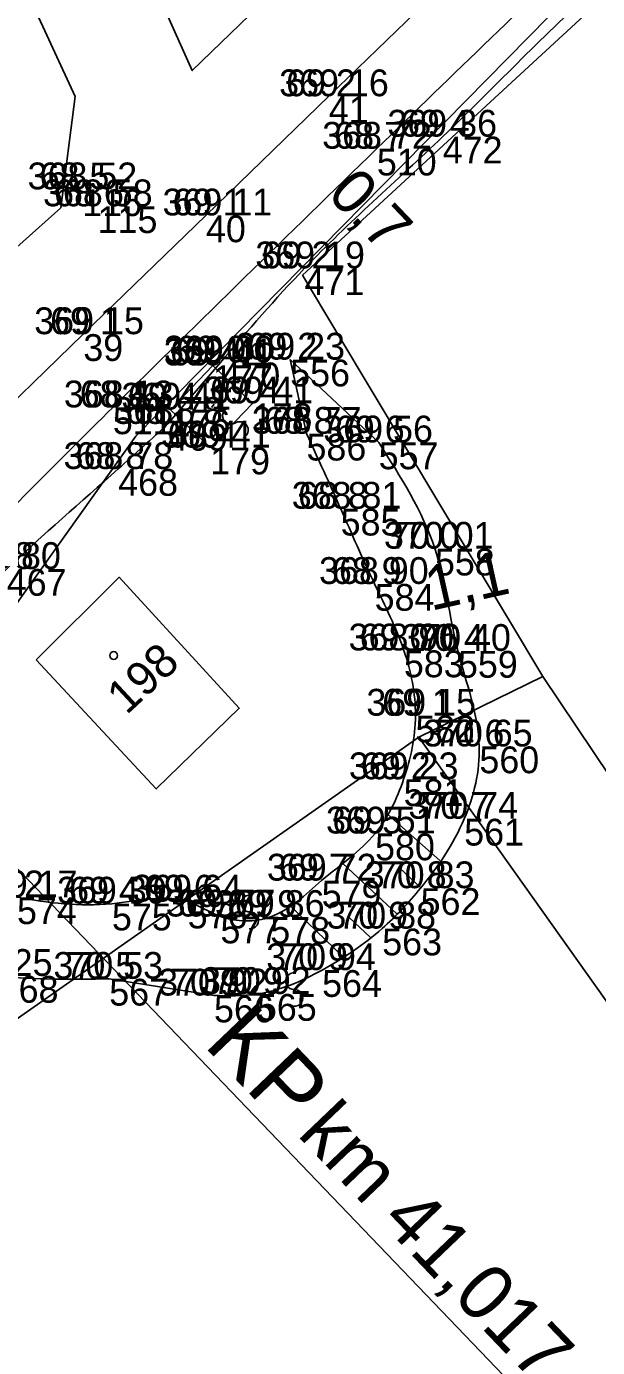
# Model space of a CAD drawing. Extents: x -514509 to -512782, y -1144610 to -1143439.
# Drawn here: x -514463.1 to -514437.5, y -1144579 to -1144519.8 of the extents above; entities that cross this region are included whole.
import ezdxf

# ---------------------------------------------------------------- set-up
doc = ezdxf.new("R2010")
doc.units = 0
for name, color, linetype in [('Vrstva 1', 7, 'Continuous'), ('Vrstva 10', 7, 'Continuous'), ('Vrstva 11', 7, 'Continuous'), ('Vrstva 18', 7, 'Continuous'), ('Vrstva 39', 7, 'Continuous'), ('Vrstva 57', 7, 'Continuous'), ('Vrstva 58', 7, 'Continuous'), ('Vrstva 59', 7, 'Continuous'), ('Vrstva 6', 7, 'Continuous'), ('Vrstva 60', 7, 'Continuous'), ('Vrstva 8', 7, 'Continuous'), ('Vrstva 9', 7, 'Continuous')]:
    doc.layers.add(name, color=color, linetype=linetype)

msp = doc.modelspace()

# ---------------------------------------------------------------- linework, layer by layer
at = {"layer": 'Vrstva 1'}
msp.add_lwpolyline([(-514486.959, -1144573.259), (-514486.512, -1144572.833), (-514479.3, -1144565.501), (-514471.808, -1144557.321), (-514458.154, -1144538.146), (-514438.738, -1144518.384)], dxfattribs=at)
at = {"layer": 'Vrstva 10'}
for points in [[(-514499.819, -1144558.314), (-514478.557, -1144543.138), (-514461.519, -1144527.903), (-514460.881, -1144522.921), (-514467.806, -1144507.951), (-514463.437, -1144504.318), (-514455.636, -1144521.761), (-514416.221, -1144483.68), (-514393.167, -1144461.734), (-514369.711, -1144436.746), (-514306.194, -1144376.041), (-514315.59, -1144367.645), (-514315.978, -1144364.474), (-514264.396, -1144333.352), (-514260.011, -1144328.496), (-514252.731, -1144315.601), (-514243.166, -1144315.871), (-514219.401, -1144293.726)], [(-514200.74, -1144295.636), (-514262.452, -1144355.017), (-514268.983, -1144370.755), (-514278.697, -1144366.838), (-514289.275, -1144383.939), (-514344.28, -1144437.349), (-514361.723, -1144450.643), (-514428.349, -1144510.282), (-514450.694, -1144530.929), (-514439.937, -1144548.904), (-514445.489, -1144551.626), (-514469.812, -1144568.673), (-514482.71, -1144578.196)], [(-514200.74, -1144295.636), (-514262.452, -1144355.017), (-514268.983, -1144370.755), (-514278.697, -1144366.838), (-514289.275, -1144383.939), (-514344.28, -1144437.349), (-514361.723, -1144450.643), (-514428.349, -1144510.282), (-514450.694, -1144530.929), (-514439.937, -1144548.904), (-514445.489, -1144551.626), (-514469.812, -1144568.673), (-514482.71, -1144578.196)], [(-514454.371, -1144534.844), (-514456.72, -1144537.59)], [(-514451.25, -1144534.708), (-514447.285, -1144538.424)], [(-514450.516, -1144538.027), (-514451.25, -1144534.708)], [(-514444.543, -1144557.155), (-514446.884, -1144555.083)], [(-514446.477, -1144559.546), (-514448.898, -1144557.287)], [(-514445.418, -1144558.36), (-514446.362, -1144557.473)], [(-514448.877, -1144561.467), (-514451.278, -1144559.151)], [(-514447.657, -1144560.601), (-514448.613, -1144559.702)], [(-514454.658, -1144563.198), (-514459.348, -1144562.45)]]:
    msp.add_lwpolyline(points, dxfattribs=at)
for points in [[(-514375.949, -1144459.095), (-514387.132, -1144469.854), (-514400.738, -1144482.57), (-514412.845, -1144493.748), (-514424.447, -1144503.796), (-514437.11, -1144515.375), (-514447.371, -1144525.258), (-514459.186, -1144536.848), (-514466.652, -1144544.376), (-514470.691, -1144548.585)], [(-514454.371, -1144534.844), (-514450.606, -1144530.619), (-514444.418, -1144524.718), (-514437.738, -1144518.212), (-514427.828, -1144509.829), (-514420.59, -1144502.963), (-514408.415, -1144492.628), (-514395.794, -1144481.427), (-514388.087, -1144474.529), (-514380.093, -1144467.923), (-514372.759, -1144462.078)], [(-514488.198, -1144571.819), (-514485.437, -1144569.212), (-514482.715, -1144566.566), (-514480.09, -1144563.83), (-514478.831, -1144562.413), (-514477.617, -1144560.954), (-514476.333, -1144559.296), (-514475.09, -1144557.61), (-514473.859, -1144555.916), (-514472.612, -1144554.233), (-514470.834, -1144551.888), (-514469.034, -1144549.558), (-514463.938, -1144544.087), (-514458.947, -1144539.607), (-514456.72, -1144537.59)], [(-514470.074, -1144558.067), (-514467.373, -1144558.131), (-514463.477, -1144558.796), (-514459.23, -1144559.085), (-514455.839, -1144558.992), (-514454.366, -1144559.66), (-514452.137, -1144559.677), (-514449.842, -1144558.049), (-514447.449, -1144555.942), (-514446.17, -1144553.512), (-514445.642, -1144550.659), (-514446.158, -1144547.737), (-514447.471, -1144544.76), (-514448.987, -1144541.391), (-514450.516, -1144538.027)], [(-514447.285, -1144538.424), (-514444.77, -1144543.177), (-514443.739, -1144547.762), (-514442.784, -1144552.042), (-514443.457, -1144555.285), (-514445.415, -1144558.39), (-514447.132, -1144560.198), (-514449.821, -1144562.057), (-514452.741, -1144563.134), (-514454.658, -1144563.198)], [(-514459.348, -1144562.45), (-514464.296, -1144562.322), (-514468.295, -1144561.563), (-514471.754, -1144560.638)]]:
    msp.add_spline(points, degree=3, dxfattribs=at)
at = {"layer": 'Vrstva 18'}
for centre, radius, start, end in [((-514453.899, -1144537.225), 0.376, 114.77011, 301.08124), ((-514453.506, -1144537.867), 0.377, 294.09407, 121.75728), ((-514453.055, -1144559.079), 0.376, 84.36247, 270.6736), ((-514453.042, -1144559.832), 0.377, 263.68642, 91.34964), ((-514451.071, -1144562.555), 0.376, 84.36247, 270.6736), ((-514451.058, -1144563.308), 0.377, 263.68642, 91.34964)]:
    msp.add_arc(centre, radius, start, end, dxfattribs=at)
at = {"layer": 'Vrstva 39'}
msp.add_lwpolyline([(-514471.348, -1144549.289), (-514439.942, -1144582.059)], dxfattribs=at)
at = {"layer": 'Vrstva 6'}
msp.add_line((-514454.776, -1144536.853), (-514454.648, -1144536.704), dxfattribs=at)
msp.add_lwpolyline([(-514493.711, -1144565.412), (-514492.396, -1144564.192), (-514486.631, -1144558.888), (-514481.255, -1144553.686), (-514473.947, -1144546.599), (-514470.451, -1144543.209), (-514465.565, -1144538.47), (-514460.514, -1144533.572), (-514455.022, -1144528.247), (-514449.52, -1144522.91), (-514443.898, -1144517.459)], dxfattribs=at)
msp.add_lwpolyline([(-514456.608, -1144536.955), (-514454.706, -1144534.97), (-514452.932, -1144536.669), (-514454.834, -1144538.654)], close=True, dxfattribs=at)
at = {"layer": 'Vrstva 60'}
for p, q in [((-514449.52, -1144522.91), (-514449.52, -1144522.91)), ((-514444.42, -1144524.72), (-514444.42, -1144524.72)), ((-514447.37, -1144525.26), (-514447.37, -1144525.26)), ((-514460.56, -1144527.08), (-514460.56, -1144527.08)), ((-514459.87, -1144527.84), (-514459.87, -1144527.84)), ((-514455.02, -1144528.25), (-514455.02, -1144528.25)), ((-514450.61, -1144530.62), (-514450.61, -1144530.62)), ((-514460.51, -1144533.57), (-514460.51, -1144533.57)), ((-514454.71, -1144534.97), (-514454.71, -1144534.97)), ((-514454.37, -1144534.84), (-514454.37, -1144534.84)), ((-514451.25, -1144534.71), (-514451.25, -1144534.71)), ((-514459.19, -1144536.85), (-514459.19, -1144536.85)), ((-514456.61, -1144536.95), (-514456.61, -1144536.95)), ((-514452.93, -1144536.67), (-514452.93, -1144536.67)), ((-514456.72, -1144537.59), (-514456.72, -1144537.59)), ((-514450.52, -1144538.03), (-514450.52, -1144538.03)), ((-514454.83, -1144538.65), (-514454.83, -1144538.65)), ((-514447.29, -1144538.42), (-514447.29, -1144538.42)), ((-514458.95, -1144539.61), (-514458.95, -1144539.61)), ((-514448.99, -1144541.39), (-514448.99, -1144541.39)), ((-514444.77, -1144543.18), (-514444.77, -1144543.18)), ((-514447.47, -1144544.76), (-514447.47, -1144544.76)), ((-514446.16, -1144547.74), (-514446.16, -1144547.74)), ((-514443.74, -1144547.76), (-514443.74, -1144547.76)), ((-514445.64, -1144550.66), (-514445.64, -1144550.66)), ((-514442.78, -1144552.04), (-514442.78, -1144552.04)), ((-514446.17, -1144553.51), (-514446.17, -1144553.51)), ((-514443.46, -1144555.28), (-514443.46, -1144555.28)), ((-514447.45, -1144555.94), (-514447.45, -1144555.94)), ((-514449.84, -1144558.05), (-514449.84, -1144558.05)), ((-514445.41, -1144558.39), (-514445.41, -1144558.39)), ((-514459.23, -1144559.08), (-514459.23, -1144559.08)), ((-514455.84, -1144558.99), (-514455.84, -1144558.99)), ((-514454.37, -1144559.66), (-514454.37, -1144559.66)), ((-514452.14, -1144559.68), (-514452.14, -1144559.68)), ((-514447.13, -1144560.2), (-514447.13, -1144560.2)), ((-514459.35, -1144562.45), (-514459.35, -1144562.45)), ((-514449.82, -1144562.06), (-514449.82, -1144562.06)), ((-514454.66, -1144563.2), (-514454.66, -1144563.2)), ((-514452.74, -1144563.13), (-514452.74, -1144563.13))]:
    msp.add_line(p, q, dxfattribs=at)
at = {"layer": 'Vrstva 8'}
msp.add_lwpolyline([(-514462.623, -1144548.157), (-514458.902, -1144544.458), (-514453.531, -1144550.331), (-514457.243, -1144553.945)], close=True, dxfattribs=at)
for points in [[(-514439.937, -1144548.904), (-514400.689, -1144607.426), (-514383.25, -1144597.943)], [(-514400.689, -1144607.426), (-514404.33, -1144609.596), (-514445.489, -1144551.626)]]:
    msp.add_lwpolyline(points, dxfattribs=at)
at = {"layer": 'Vrstva 9'}
msp.add_circle((-514459.149, -1144547.967), 0.175, dxfattribs=at)

# ---------------------------------------------------------------- texts
at = {"layer": 'Vrstva 11'}
for s, rotation, p in [('0,7', 313.64186, (-514449.647, -1144527.333)), ('1,1', 12.58002, (-514444.949, -1144545.969))]:
    msp.add_text(s, height=2, rotation=rotation, dxfattribs=at).set_placement(p)
at = {"layer": 'Vrstva 39'}
for s, height, p in [('KP', 3, (-514455.167, -1144565.423)), ('km 41,017', 2.5, (-514450.976, -1144569.442))]:
    msp.add_text(s, height=height, rotation=313.73264, dxfattribs=at).set_placement(p)
at = {"layer": 'Vrstva 57'}
for s, p in [('69 2 ', (-514451.434, -1144522.91)), ('69 4 ', (-514446.334, -1144524.72)), ('68 7 ', (-514449.278, -1144525.26)), ('68 5 ', (-514462.468, -1144527.08)), ('68 6 ', (-514461.818, -1144527.84)), ('69 1 ', (-514456.51, -1144528.25)), ('69 2 ', (-514452.524, -1144530.62)), ('69 1 ', (-514462, -1144533.57)), ('69 2 ', (-514453.164, -1144534.71)), ('69 4 ', (-514456.624, -1144534.97)), ('69 0 ', (-514456.35, -1144534.84)), ('68 1 ', (-514460.672, -1144536.85)), ('69 4 ', (-514458.524, -1144536.95)), ('69 4 ', (-514454.844, -1144536.67)), ('68 8 ', (-514458.628, -1144537.59)), ('68 8 ', (-514452.428, -1144538.03)), ('69 4 ', (-514456.744, -1144538.65)), ('69 6 ', (-514449.246, -1144538.42)), ('68 8 ', (-514460.858, -1144539.61)), ('68 8 ', (-514450.898, -1144541.39)), ('70 0 ', (-514446.796, -1144543.18)), ('68 8 ', (-514465.848, -1144544.09)), ('68 9 ', (-514449.383, -1144544.76)), ('69 0 ', (-514448.14, -1144547.74)), ('70 4 ', (-514445.7, -1144547.76)), ('69 1 ', (-514447.13, -1144550.66)), ('70 6 ', (-514444.782, -1144552.04)), ('69 2 ', (-514448.084, -1144553.51)), ('70 7 ', (-514445.42, -1144555.28)), ('69 5 ', (-514449.364, -1144555.94)), ('69 7 ', (-514451.754, -1144558.05)), ('70 8 ', (-514447.37, -1144558.39)), ('69 2 ', (-514465.394, -1144558.8)), ('69 4 ', (-514461.144, -1144559.08)), ('69 6 ', (-514457.796, -1144558.99)), ('69 8 ', (-514456.284, -1144559.66)), ('69 9 ', (-514454.06, -1144559.68)), ('70 9 ', (-514449.096, -1144560.2)), ('70 5 ', (-514461.31, -1144562.45)), ('70 9 ', (-514451.786, -1144562.06)), ('70 9 ', (-514454.706, -1144563.13)), ('70 9 ', (-514456.626, -1144563.2))]:
    msp.add_text(s, height=1.2, dxfattribs=at).set_placement(p)
at = {"layer": 'Vrstva 58'}
for s, p in [('369 16', (-514451.742, -1144522.91)), ('369 36', (-514446.898, -1144524.72)), ('368 72', (-514449.816, -1144525.26)), ('368 52', (-514463.006, -1144527.08)), ('368 58', (-514462.316, -1144527.84)), ('369 11', (-514456.963, -1144528.25)), ('369 19', (-514452.811, -1144530.62)), ('369 15', (-514462.708, -1144533.57)), ('369 23', (-514453.702, -1144534.71)), ('369 41', (-514456.908, -1144534.97)), ('369 00', (-514456.9, -1144534.84)), ('368 13', (-514461.38, -1144536.85)), ('369 41', (-514458.808, -1144536.95)), ('369 41', (-514455.128, -1144536.67)), ('368 78', (-514459.166, -1144537.59)), ('368 77', (-514452.966, -1144538.03)), ('369 41', (-514457.028, -1144538.65)), ('369 56', (-514449.768, -1144538.42)), ('368 78', (-514461.396, -1144539.61)), ('368 81', (-514451.18, -1144541.39)), ('370 01', (-514447.052, -1144543.18)), ('368 80', (-514466.424, -1144544.09)), ('368 90', (-514449.958, -1144544.76)), ('368 96', (-514448.634, -1144547.74)), ('370 40', (-514446.278, -1144547.76)), ('369 15', (-514447.838, -1144550.66)), ('370 65', (-514445.304, -1144552.04)), ('369 23', (-514448.622, -1144553.51)), ('370 74', (-514445.958, -1144555.28)), ('369 51', (-514449.648, -1144555.94)), ('369 72', (-514452.292, -1144558.05)), ('370 83', (-514447.908, -1144558.39)), ('369 17', (-514465.678, -1144558.8)), ('369 39', (-514461.686, -1144559.08)), ('369 64', (-514458.318, -1144558.99)), ('369 77', (-514456.822, -1144559.66)), ('369 86', (-514454.618, -1144559.68)), ('370 88', (-514449.628, -1144560.2)), ('370 25', (-514466.798, -1144562.32)), ('370 53', (-514461.848, -1144562.45)), ('370 94', (-514452.322, -1144562.06)), ('370 92', (-514455.242, -1144563.13)), ('370 92', (-514457.162, -1144563.2))]:
    msp.add_text(s, height=1.2, dxfattribs=at).set_placement(p)
at = {"layer": 'Vrstva 59'}
for s, p in [('41', (-514449.52, -1144524.11)), ('472', (-514444.42, -1144525.92)), ('510', (-514447.37, -1144526.46)), ('116', (-514460.56, -1144528.28)), ('115', (-514459.87, -1144529.04)), ('40', (-514455.02, -1144529.45)), ('471', (-514450.61, -1144531.82)), ('39', (-514460.51, -1144534.77)), ('177', (-514454.71, -1144536.17)), ('470', (-514454.37, -1144536.04)), ('556', (-514451.25, -1144535.91)), ('511', (-514459.19, -1144538.05)), ('176', (-514456.61, -1144538.15)), ('178', (-514452.93, -1144537.87)), ('469', (-514456.72, -1144538.79)), ('586', (-514450.52, -1144539.23)), ('179', (-514454.83, -1144539.85)), ('557', (-514447.29, -1144539.62)), ('468', (-514458.95, -1144540.81)), ('585', (-514448.99, -1144542.59)), ('558', (-514444.77, -1144544.38)), ('467', (-514463.94, -1144545.29)), ('584', (-514447.47, -1144545.96)), ('583', (-514446.16, -1144548.94)), ('559', (-514443.74, -1144548.96)), ('582', (-514445.64, -1144551.86)), ('560', (-514442.78, -1144553.24)), ('581', (-514446.17, -1144554.71)), ('561', (-514443.46, -1144556.48)), ('580', (-514447.45, -1144557.14)), ('579', (-514449.84, -1144559.25)), ('574', (-514463.48, -1144560)), ('562', (-514445.41, -1144559.59)), ('575', (-514459.23, -1144560.28)), ('576', (-514455.84, -1144560.19)), ('577', (-514454.37, -1144560.86)), ('578', (-514452.14, -1144560.88)), ('563', (-514447.13, -1144561.4)), ('568', (-514464.3, -1144563.52)), ('567', (-514459.35, -1144563.65)), ('564', (-514449.82, -1144563.26)), ('566', (-514454.66, -1144564.4)), ('565', (-514452.74, -1144564.33))]:
    msp.add_text(s, height=1.2, dxfattribs=at).set_placement(p)
at = {"layer": 'Vrstva 9'}
msp.add_text('198', height=1.5, rotation=42.81929, dxfattribs=at).set_placement((-514458.578, -1144550.656))

doc.saveas('drawing.dxf')
